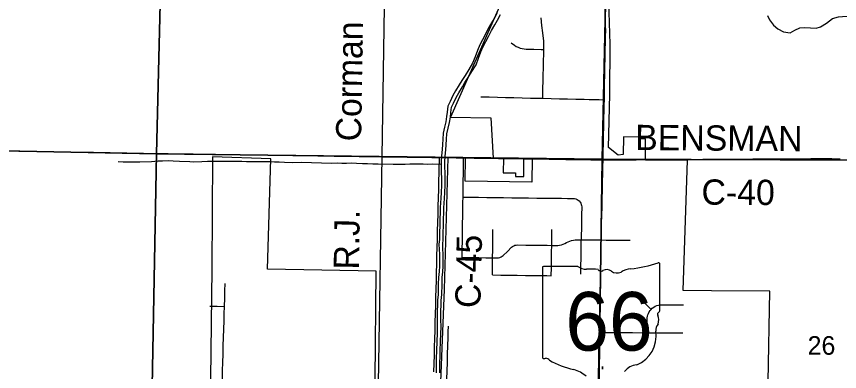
# Model space of a CAD drawing. Extents: x 0 to 34, y 0 to 22.
# Drawn here: x 4.43 to 6.279, y 14.929 to 15.728 of the extents above; entities that cross this region are included whole.
import ezdxf

# ---------------------------------------------------------------- set-up
doc = ezdxf.new("R2010")
doc.units = 0
for name, color, linetype in [('GM_X_City_Street', 7, 'Continuous'), ('GM_X_Corporation', 7, 'Continuous'), ('GM_X_County_Road', 7, 'Continuous'), ('GM_X_County_Road_Text', 7, 'Continuous'), ('GM_X_Minor_River', 7, 'Continuous'), ('GM_X_Rail_Line', 7, 'Continuous'), ('GM_X_Rail_Line_Text', 7, 'Continuous'), ('GM_X_Section_Text', 7, 'Continuous'), ('GM_X_State_Location', 7, 'Continuous'), ('GM_X_State_Route', 7, 'Continuous'), ('GM_X_State_Shield', 7, 'Continuous')]:
    doc.layers.add(name, color=color, linetype=linetype)

msp = doc.modelspace()

# ---------------------------------------------------------------- linework, layer by layer
at = {"layer": 'GM_X_City_Street'}
for points in [[(5.6123, 15.5436), (5.6126, 15.5544), (5.6128, 15.5651), (5.6132, 15.5837), (5.6135, 15.5973), (5.6138, 15.6109), (5.6142, 15.6295), (5.6145, 15.6415), (5.6147, 15.6535), (5.6149, 15.6622), (5.6145, 15.6722), (5.6124, 15.6907), (5.6105, 15.7076), (5.6087, 15.7245)], [(5.5416, 15.668), (5.5488, 15.6629), (5.5527, 15.6604), (5.5569, 15.6584), (5.5612, 15.6567), (5.5657, 15.6555), (5.5703, 15.6547), (5.5749, 15.6544), (5.592, 15.654), (5.609, 15.6536), (5.6147, 15.6535)], [(5.473, 15.547), (5.4916, 15.5466), (5.5103, 15.5461), (5.5289, 15.5457), (5.5475, 15.5452), (5.5662, 15.5448), (5.5848, 15.5443), (5.5986, 15.544), (5.6123, 15.5436), (5.631, 15.5432), (5.6496, 15.5427), (5.6682, 15.5423), (5.6869, 15.5418), (5.7055, 15.5414), (5.7162, 15.5411), (5.7269, 15.5409), (5.7387, 15.5406), (5.7506, 15.5403)], [(5.4313, 15.1859), (5.4316, 15.2046), (5.4319, 15.2232), (5.4321, 15.2418), (5.4324, 15.2605), (5.4327, 15.2791), (5.4329, 15.2978), (5.4331, 15.3096), (5.4333, 15.3215), (5.4335, 15.339), (5.4338, 15.3564), (5.4341, 15.375), (5.4343, 15.388), (5.4344, 15.4011), (5.4346, 15.4097)], [(5.4333, 15.3215), (5.4495, 15.3213), (5.4682, 15.3211), (5.4868, 15.3209), (5.5054, 15.3206), (5.5241, 15.3204), (5.5427, 15.3202), (5.5614, 15.3199), (5.58, 15.3197), (5.5987, 15.3195), (5.6173, 15.3193), (5.6359, 15.319), (5.6546, 15.3188), (5.6678, 15.3186), (5.681, 15.3185), (5.6839, 15.3182), (5.6868, 15.3175), (5.6896, 15.3163), (5.6921, 15.3147), (5.6943, 15.3128), (5.6962, 15.3105), (5.6977, 15.3079), (5.6988, 15.3052), (5.6995, 15.3023), (5.6997, 15.2993), (5.6995, 15.2807), (5.6992, 15.262), (5.6991, 15.2494), (5.6989, 15.2367), (5.6988, 15.2255)], [(5.4996, 15.1851), (5.4998, 15.2037), (5.5, 15.2224), (5.5002, 15.2355), (5.5004, 15.2487)], [(5.6323, 15.213), (5.6325, 15.231), (5.6328, 15.249)], [(5.4313, 15.1859), (5.45, 15.1857), (5.4686, 15.1855), (5.4841, 15.1853), (5.4996, 15.1851), (5.51, 15.185), (5.513, 15.1852), (5.5159, 15.1858), (5.5186, 15.1869), (5.5212, 15.1884), (5.5235, 15.1903), (5.5328, 15.1995), (5.5422, 15.2086), (5.5444, 15.2105), (5.547, 15.212), (5.5498, 15.2131), (5.5527, 15.2138), (5.5556, 15.214), (5.5743, 15.2137), (5.5929, 15.2135), (5.6115, 15.2133), (5.6219, 15.2131), (5.6323, 15.213), (5.6418, 15.2129), (5.6459, 15.213), (5.6501, 15.2136), (5.6541, 15.2144), (5.6581, 15.2157), (5.6619, 15.2173), (5.6656, 15.2193), (5.6692, 15.2212), (5.673, 15.2228), (5.677, 15.2241), (5.681, 15.225), (5.6852, 15.2255), (5.6893, 15.2256), (5.6988, 15.2255), (5.7081, 15.2254), (5.726, 15.2252), (5.7438, 15.2251)], [(5.6978, 15.1479), (5.6981, 15.1665), (5.6983, 15.1851), (5.6985, 15.2014), (5.6987, 15.2177), (5.6988, 15.2255)], [(5.7438, 15.2251), (5.7544, 15.225), (5.7731, 15.2249), (5.7907, 15.2247), (5.8084, 15.2246)], [(5.6315, 15.1448), (5.6317, 15.1635), (5.6319, 15.1821), (5.6321, 15.1976), (5.6323, 15.213)], [(5.4991, 15.1465), (5.4993, 15.1651), (5.4995, 15.1751), (5.4996, 15.1851)], [(5.4991, 15.1465), (5.5178, 15.1462), (5.5364, 15.146), (5.555, 15.1458), (5.5737, 15.1455), (5.5923, 15.1453), (5.611, 15.1451), (5.6212, 15.145), (5.6315, 15.1448)], [(4.8926, 14.9127), (4.8932, 14.9314), (4.8937, 14.95), (4.8943, 14.9686), (4.8948, 14.9873), (4.8954, 15.0059), (4.8959, 15.0245), (4.8965, 15.0432), (4.8969, 15.0594), (4.8974, 15.0755), (4.898, 15.0942), (4.8984, 15.1109), (4.8989, 15.1276)], [(5.8555, 15.069), (5.8511, 15.0734), (5.8423, 15.0823), (5.8405, 15.0847), (5.8401, 15.0872), (5.8402, 15.0894)], [(4.8643, 15.0765), (4.8809, 15.076), (4.8974, 15.0755)], [(5.8466, 15.0167), (5.8467, 15.0334), (5.8469, 15.0501), (5.8475, 15.0535), (5.8484, 15.0569), (5.8497, 15.0602), (5.8513, 15.0633), (5.8533, 15.0663), (5.8555, 15.069), (5.8584, 15.0717), (5.8615, 15.074), (5.8649, 15.076), (5.8684, 15.0776), (5.8722, 15.0787), (5.876, 15.0794), (5.8799, 15.0796), (5.8986, 15.0795), (5.9282, 15.0794)], [(5.3967, 14.9023), (5.397, 14.9125), (5.3976, 14.9311), (5.3981, 14.9497), (5.3987, 14.9684), (5.3993, 14.987), (5.3998, 15.0057), (5.4002, 15.0185), (5.4006, 15.0314)], [(5.7395, 15.0171), (5.7581, 15.017), (5.7954, 15.0169), (5.8135, 15.0168)], [(5.8135, 15.0168), (5.8466, 15.0167), (5.8652, 15.0167), (5.9025, 15.0166), (5.927, 15.0165)]]:
    msp.add_lwpolyline(points, dxfattribs=at)
at = {"layer": 'GM_X_Corporation'}
for points in [[(4.7695, 16.4317), (4.7451, 15.4188), (3.745, 15.438), (3.7672, 16.4521)], [(5.7675, 16.4186), (5.7454, 15.4068), (4.7451, 15.4188), (4.7695, 16.4317)], [(5.7675, 16.4186), (6.7694, 16.4145), (6.7449, 15.4031), (5.7454, 15.4068)], [(4.7451, 15.4188), (4.7262, 14.4138), (3.7208, 14.432), (3.745, 15.438)], [(5.7454, 15.4068), (5.7313, 14.4009), (4.7262, 14.4138), (4.7451, 15.4188)], [(5.7454, 15.4068), (6.7449, 15.4031), (6.7333, 14.3908), (5.7313, 14.4009)], [(5.7468, 14.9406), (5.7467, 14.9345), (5.7467, 14.9359)]]:
    msp.add_lwpolyline(points, close=True, dxfattribs=at)
for points in [[(5.5294, 15.783), (5.405, 15.5014), (5.4958, 15.5), (5.5008, 15.409), (5.5239, 15.4088), (5.5234, 15.3759), (5.5508, 15.3763), (5.5507, 15.3675), (5.5695, 15.3677), (5.5701, 15.4084), (5.5886, 15.4082), (5.5877, 15.3554), (5.4377, 15.3575), (5.4384, 15.4101), (5.3989, 15.4106), (5.3911, 15.1138), (5.3824, 14.9065)], [(6.3151, 14.6439), (6.2359, 14.6444), (6.24, 14.905), (6.1189, 14.9061), (6.1226, 15.1104), (5.9911, 15.1111), (5.9277, 15.1114), (5.9374, 15.4043), (5.843, 15.4049), (5.8429, 15.4522), (5.8315, 15.4524), (5.8315, 15.4566), (5.7936, 15.4571), (5.7929, 15.4172), (5.7815, 15.4161), (5.7603, 15.4329), (5.763, 15.5521), (5.7636, 15.6652), (5.7608, 15.7611)], [(5.2358, 14.9109), (5.2383, 15.1553), (4.9943, 15.1596), (5.0015, 15.4077), (4.8702, 15.4122), (4.8689, 15.1602), (4.8663, 14.9129)]]:
    msp.add_lwpolyline(points, dxfattribs=at)
at = {"layer": 'GM_X_County_Road'}
msp.add_line((5.9359, 15.4063), (5.9388, 15.4063), dxfattribs=at)
for points in [[(5.3679, 14.9287), (5.3684, 14.9473), (5.3689, 14.966), (5.3694, 14.9846), (5.3699, 15.0032), (5.3704, 15.0219), (5.3709, 15.0405), (5.3713, 15.0591), (5.3718, 15.0778), (5.3723, 15.0964), (5.3728, 15.115), (5.3733, 15.1337), (5.3738, 15.1523), (5.3742, 15.171), (5.3747, 15.1896), (5.3752, 15.2082), (5.3757, 15.2269), (5.3762, 15.2455), (5.3767, 15.2641), (5.3771, 15.2828), (5.3776, 15.3014), (5.3781, 15.32), (5.3786, 15.3387), (5.3791, 15.3573), (5.3795, 15.3759), (5.3799, 15.3892), (5.3802, 15.4024), (5.3804, 15.4105)], [(5.7476, 15.4052), (5.7663, 15.4053), (5.7849, 15.4054), (5.8036, 15.4055), (5.8222, 15.4056), (5.8333, 15.4057), (5.8444, 15.4058)], [(5.8444, 15.4058), (5.863, 15.4059), (5.8817, 15.406), (5.9003, 15.4061), (5.9176, 15.4062), (5.9349, 15.4063), (5.9359, 15.4063)], [(5.9388, 15.4063), (5.9536, 15.4064), (5.9722, 15.4065), (5.9908, 15.4066), (6.0095, 15.4068), (6.0281, 15.4069), (6.0468, 15.407), (6.0654, 15.4071), (6.0841, 15.4072), (6.1027, 15.4073), (6.1213, 15.4074), (6.14, 15.4075), (6.1586, 15.4077), (6.1773, 15.4078), (6.1959, 15.4079), (6.2145, 15.408), (6.2287, 15.4081), (6.2428, 15.4082), (6.2615, 15.408), (6.2801, 15.4078)]]:
    msp.add_lwpolyline(points, dxfattribs=at)
at = {"layer": 'GM_X_Minor_River'}
for points in [[(5.5098, 15.7359), (5.5034, 15.7231), (5.4975, 15.713), (5.49, 15.7003), (5.4832, 15.6864), (5.4769, 15.6751), (5.4709, 15.6635), (5.4657, 15.6511), (5.4605, 15.6371), (5.4548, 15.6228), (5.4462, 15.6082), (5.4379, 15.5951), (5.4304, 15.5835), (5.4249, 15.5738), (5.4166, 15.5603), (5.4103, 15.5498), (5.404, 15.5367), (5.3988, 15.5262), (5.3973, 15.5125), (5.3964, 15.5027), (5.3946, 15.4909), (5.3916, 15.4785), (5.3887, 15.4649), (5.3876, 15.452), (5.3873, 15.4398), (5.3863, 15.4288), (5.3849, 15.414), (5.3842, 15.4008), (5.3839, 15.3894), (5.3844, 15.3761), (5.3845, 15.3651), (5.3845, 15.3483), (5.3838, 15.332), (5.3831, 15.3191), (5.3818, 15.2979), (5.3816, 15.2865), (5.3813, 15.2732), (5.3802, 15.2265), (5.3792, 15.2159), (5.3793, 15.2041), (5.3802, 15.1935), (5.3803, 15.1798), (5.38, 15.1665), (5.3793, 15.154), (5.3783, 15.1411), (5.3776, 15.1256), (5.377, 15.1028), (5.376, 15.0895), (5.3757, 15.0789), (5.3751, 15.0656), (5.3753, 15.0443), (5.3754, 15.0322), (5.375, 15.0121), (5.3743, 15.0003), (5.3737, 14.973), (5.3731, 14.9627), (5.3728, 14.9498), (5.3729, 14.9384), (5.3727, 14.9267)], [(5.3811, 14.9266), (5.3813, 14.9384), (5.3812, 14.9498), (5.3815, 14.9624), (5.3821, 14.9726), (5.3827, 15), (5.3834, 15.0117), (5.3838, 15.0321), (5.3837, 15.0444), (5.3835, 15.0655), (5.3841, 15.0786), (5.3844, 15.0891), (5.3854, 15.1024), (5.386, 15.1253), (5.3867, 15.1406), (5.3877, 15.1534), (5.3884, 15.1662), (5.3887, 15.1797), (5.3886, 15.1939), (5.3877, 15.2045), (5.3876, 15.2156), (5.3886, 15.226), (5.3897, 15.273), (5.39, 15.2863), (5.3903, 15.2976), (5.3915, 15.3187), (5.3922, 15.3316), (5.3929, 15.3482), (5.3929, 15.3651), (5.3928, 15.3763), (5.3923, 15.3894), (5.3926, 15.4005), (5.3933, 15.4134), (5.3947, 15.428), (5.3957, 15.4393), (5.396, 15.4515), (5.397, 15.4636), (5.3998, 15.4766), (5.4028, 15.4893), (5.4047, 15.5016), (5.4057, 15.5117), (5.407, 15.5238), (5.4115, 15.533), (5.4177, 15.5458), (5.4238, 15.5559), (5.4321, 15.5695), (5.4376, 15.5792), (5.445, 15.5906), (5.4533, 15.6038), (5.4624, 15.6191), (5.4683, 15.6341), (5.4735, 15.648), (5.4786, 15.6599), (5.4843, 15.6711), (5.4907, 15.6825), (5.4974, 15.6963), (5.5047, 15.7088), (5.5108, 15.7191), (5.5173, 15.7321)], [(6.1168, 15.73), (6.1214, 15.72), (6.1302, 15.7077), (6.1406, 15.6998), (6.1533, 15.693), (6.1681, 15.6911), (6.1781, 15.6965), (6.1896, 15.7023), (6.2003, 15.7028), (6.2135, 15.7017), (6.2264, 15.701), (6.236, 15.7041), (6.2498, 15.7125), (6.263, 15.7232), (6.2764, 15.7266), (6.2859, 15.7275), (6.2977, 15.7283)], [(5.384, 15.3947), (5.3643, 15.3952), (5.3541, 15.395), (5.3435, 15.3956), (5.3279, 15.3956), (5.3139, 15.3956), (5.3029, 15.3951), (5.2881, 15.395), (5.2763, 15.3949), (5.2426, 15.3957), (5.2304, 15.3956), (5.2183, 15.3963), (5.2077, 15.3965), (5.1941, 15.3972), (5.1827, 15.3975), (5.1717, 15.3974), (5.161, 15.3972), (5.1508, 15.3975), (5.1387, 15.3974), (5.1155, 15.3979), (5.0932, 15.3988), (5.0704, 15.399), (5.0511, 15.3987), (5.0321, 15.3991), (5.02, 15.3998), (5.0101, 15.4004), (4.9999, 15.4006), (4.99, 15.4008), (4.9749, 15.4008), (4.9605, 15.4008), (4.9472, 15.4011), (4.9366, 15.4017), (4.9222, 15.4013), (4.9104, 15.4012), (4.9005, 15.4014), (4.8865, 15.4013), (4.8694, 15.4017), (4.8596, 15.4016), (4.8467, 15.4011), (4.8288, 15.4004), (4.8193, 15.4006), (4.7966, 15.4019), (4.7818, 15.4026), (4.7716, 15.4029), (4.7583, 15.4024), (4.7481, 15.4023), (4.7336, 15.4011), (4.707, 15.4002), (4.6949, 15.4001), (4.6816, 15.4), (4.6699, 15.3999), (4.6589, 15.4006)]]:
    msp.add_lwpolyline(points, dxfattribs=at)
at = {"layer": 'GM_X_Rail_Line'}
msp.add_lwpolyline([(5.2312, 14.404), (5.2346, 14.4124), (5.2368, 14.4226), (5.243, 14.9028), (5.2517, 15.4121), (5.2672, 16.4237), (5.283, 17.4313), (5.2899, 17.8728), (5.3076, 19.0241), (5.3057, 19.0962), (5.3011, 19.1491), (5.2883, 19.2066), (5.0953, 19.84), (5.0724, 19.9157), (5.0587, 19.9632), (5.0513, 20.0198), (5.0584, 20.4524), (5.0684, 20.9)], dxfattribs=at)
at = {"layer": 'GM_X_State_Route'}
msp.add_line((5.7388, 14.9849), (5.7388, 14.9858), dxfattribs=at)
for points in [[(5.7531, 15.6717), (5.7533, 15.6831), (5.7536, 15.6954), (5.7534, 15.7063), (5.7533, 15.7173), (5.7529, 15.7282), (5.7525, 15.7391), (5.752, 15.7501), (5.7514, 15.761), (5.7506, 15.7719), (5.7498, 15.7828), (5.7487, 15.7937), (5.7477, 15.8046), (5.7465, 15.8155), (5.7452, 15.8263), (5.7438, 15.8372), (5.7423, 15.848), (5.7409, 15.8573), (5.7381, 15.8757), (5.7354, 15.8932), (5.7327, 15.9107)], [(5.7476, 15.4052), (5.748, 15.4238), (5.7484, 15.4425), (5.7488, 15.4611), (5.7492, 15.4797), (5.7497, 15.4984), (5.7501, 15.517), (5.7503, 15.5286), (5.7506, 15.5403), (5.7509, 15.5589), (5.7513, 15.5776), (5.7516, 15.5962), (5.752, 15.6148), (5.7524, 15.6335), (5.7527, 15.6521), (5.7531, 15.6707), (5.7531, 15.6717)], [(4.4172, 15.4255), (4.4358, 15.4251), (4.4545, 15.4248), (4.4731, 15.4245), (4.4917, 15.4242), (4.5104, 15.4238), (4.529, 15.4235), (4.5477, 15.4232), (4.5663, 15.4229), (4.5849, 15.4225), (4.6036, 15.4222), (4.6222, 15.4219), (4.6409, 15.4216), (4.6595, 15.4212), (4.6781, 15.4209), (4.6968, 15.4206), (4.7154, 15.4203), (4.734, 15.4199), (4.7526, 15.4196), (4.7713, 15.4193), (4.789, 15.4191)], [(4.789, 15.4191), (4.7899, 15.4191), (4.8086, 15.4188), (4.8272, 15.4185), (4.8459, 15.4182), (4.8645, 15.418), (4.8774, 15.4178)], [(4.8774, 15.4178), (4.9018, 15.4174), (4.9204, 15.4172), (4.9391, 15.4169), (4.9577, 15.4166), (4.9763, 15.4164), (4.995, 15.4161), (5.0024, 15.416)], [(5.0024, 15.416), (5.0136, 15.4158), (5.0323, 15.4155), (5.0509, 15.4153), (5.0695, 15.415), (5.0882, 15.4147), (5.1068, 15.4145), (5.1255, 15.4142), (5.1441, 15.4139), (5.1628, 15.4137), (5.1814, 15.4134), (5.2, 15.4131), (5.2187, 15.4128), (5.2354, 15.4126), (5.252, 15.4124), (5.2707, 15.4121), (5.2893, 15.4118), (5.3079, 15.4116), (5.3266, 15.4113), (5.3452, 15.411), (5.3628, 15.4108), (5.3804, 15.4105), (5.3904, 15.4104), (5.4004, 15.4102)], [(5.4004, 15.4102), (5.4175, 15.41), (5.4346, 15.4097), (5.439, 15.4097)], [(5.439, 15.4097), (5.4492, 15.4095), (5.4584, 15.4094)], [(5.4584, 15.4094), (5.4594, 15.4094), (5.478, 15.4091), (5.4899, 15.4089), (5.5007, 15.4088)], [(5.5007, 15.4088), (5.5017, 15.4087), (5.5129, 15.4086), (5.5231, 15.4084)], [(5.5231, 15.4084), (5.5241, 15.4084), (5.5427, 15.4082), (5.5566, 15.408), (5.5695, 15.4078)], [(5.5695, 15.4078), (5.5705, 15.4078), (5.58, 15.4076), (5.5885, 15.4075)], [(5.5885, 15.4075), (5.5894, 15.4075), (5.608, 15.4072), (5.6267, 15.4069), (5.6453, 15.4067), (5.664, 15.4064), (5.6826, 15.4061), (5.7012, 15.4059), (5.7199, 15.4056), (5.7338, 15.4054), (5.7476, 15.4052)], [(5.7438, 15.2251), (5.7442, 15.2437), (5.7446, 15.2623), (5.745, 15.281), (5.7454, 15.2996), (5.7458, 15.3182), (5.7462, 15.3369), (5.7466, 15.3555), (5.747, 15.3742), (5.7473, 15.3897), (5.7476, 15.4052)], [(5.7395, 15.0171), (5.7399, 15.0357), (5.7403, 15.0544), (5.7406, 15.073), (5.741, 15.0916), (5.7414, 15.1103), (5.7418, 15.1289), (5.7422, 15.1475), (5.7426, 15.1662), (5.743, 15.1848), (5.7434, 15.2034), (5.7436, 15.2143), (5.7438, 15.2251)], [(5.7388, 14.9858), (5.7391, 15.0015), (5.7395, 15.0171)], [(5.737, 14.8972), (5.7373, 14.9125), (5.7376, 14.9278), (5.738, 14.9465), (5.7384, 14.9651), (5.7386, 14.9755), (5.7388, 14.9849)]]:
    msp.add_lwpolyline(points, dxfattribs=at)
at = {"layer": 'GM_X_State_Shield'}
for p, q in [((5.6115, 15.1624), (5.6115, 14.9622)), ((5.6913, 15.1658), (5.6141, 15.1658)), ((5.8751, 15.0661), (5.8751, 15.1708)), ((5.8751, 15.0661), (5.8751, 15.0661))]:
    msp.add_line(p, q, dxfattribs=at)
for centre, radius, start, end in [((5.6145, 15.1628), 0.00305, 98.1301, 188.1301), ((5.7097, 15.189), 0.0296, 231.6195, 271.1119), ((5.7195, 15.0535), 0.1064, 80.4867, 94.9883), ((5.8169, 15.1047), 0.0563, 97.3462, 120.7689), ((5.7812, 15.4386), 0.2796, 275.8445, 288.9065), ((5.8722, 15.1712), 0.00294, 351.8621, 97.738), ((5.7436, 15.1638), 0.00855, 219.7921, 297.1024), ((5.7562, 15.1407), 0.0178, 54.4667, 119.1411), ((5.7791, 15.1724), 0.0214, 233.8562, 294.8282), ((5.8744, 15.0584), 0.00454, 107.944, 210.337), ((5.8455, 15.0452), 0.0273, 340.033, 23.6496), ((5.872, 15.0657), 0.00314, 289.6038, 7.7341), ((5.8856, 15.0223), 0.0198, 136.8065, 186.9296), ((5.7969, 15.009), 0.0699, 292.3089, 8.9858), ((5.6145, 14.9618), 0.00308, 171.9584, 258.3066), ((5.615, 14.9823), 0.0235, 267.339, 280.6039), ((5.6198, 14.9507), 0.00848, 29.7484, 93.2717), ((5.7268, 15.1305), 0.2019, 240.4129, 257.1985), ((5.8264, 14.9061), 0.0383, 94.4031, 142.5768), ((5.6666, 14.8723), 0.0632, 47.1842, 75.836)]:
    msp.add_arc(centre, radius, start, end, dxfattribs=at)

# ---------------------------------------------------------------- texts
at = {"layer": 'GM_X_County_Road_Text'}
for s, rotation, p in [('BENSMAN', 359.579, (5.8197, 15.4273)), ('C-40', 359.6571, (5.9687, 15.3046)), ('C-45', 88.6283, (5.4721, 15.0716))]:
    msp.add_text(s, height=0.05682, rotation=rotation, dxfattribs=at).set_placement(p)
at = {"layer": 'GM_X_Rail_Line_Text'}
for s, rotation, p in [('Corman', 89.0658, (5.2042, 15.4466)), ('R.J.', 89.0064, (5.1992, 15.1583))]:
    msp.add_text(s, height=0.05663, rotation=rotation, dxfattribs=at).set_placement(p)
at = {"layer": 'GM_X_Section_Text'}
msp.add_text('26', height=0.04186, rotation=0, dxfattribs=at).set_placement((6.2072, 14.9671))
at = {"layer": 'GM_X_State_Location'}
for s in ['s', 'r']:
    msp.add_text(s, height=0.000189, dxfattribs=at).set_placement((5.7403, 15.049))
msp.add_text('66', height=0.000189, rotation=0, dxfattribs=at).set_placement((5.6926, 15.0352))
at = {"layer": 'GM_X_State_Shield'}
msp.add_text('66', height=0.13184, dxfattribs=at).set_placement((5.663, 14.9764))

doc.saveas('drawing.dxf')
